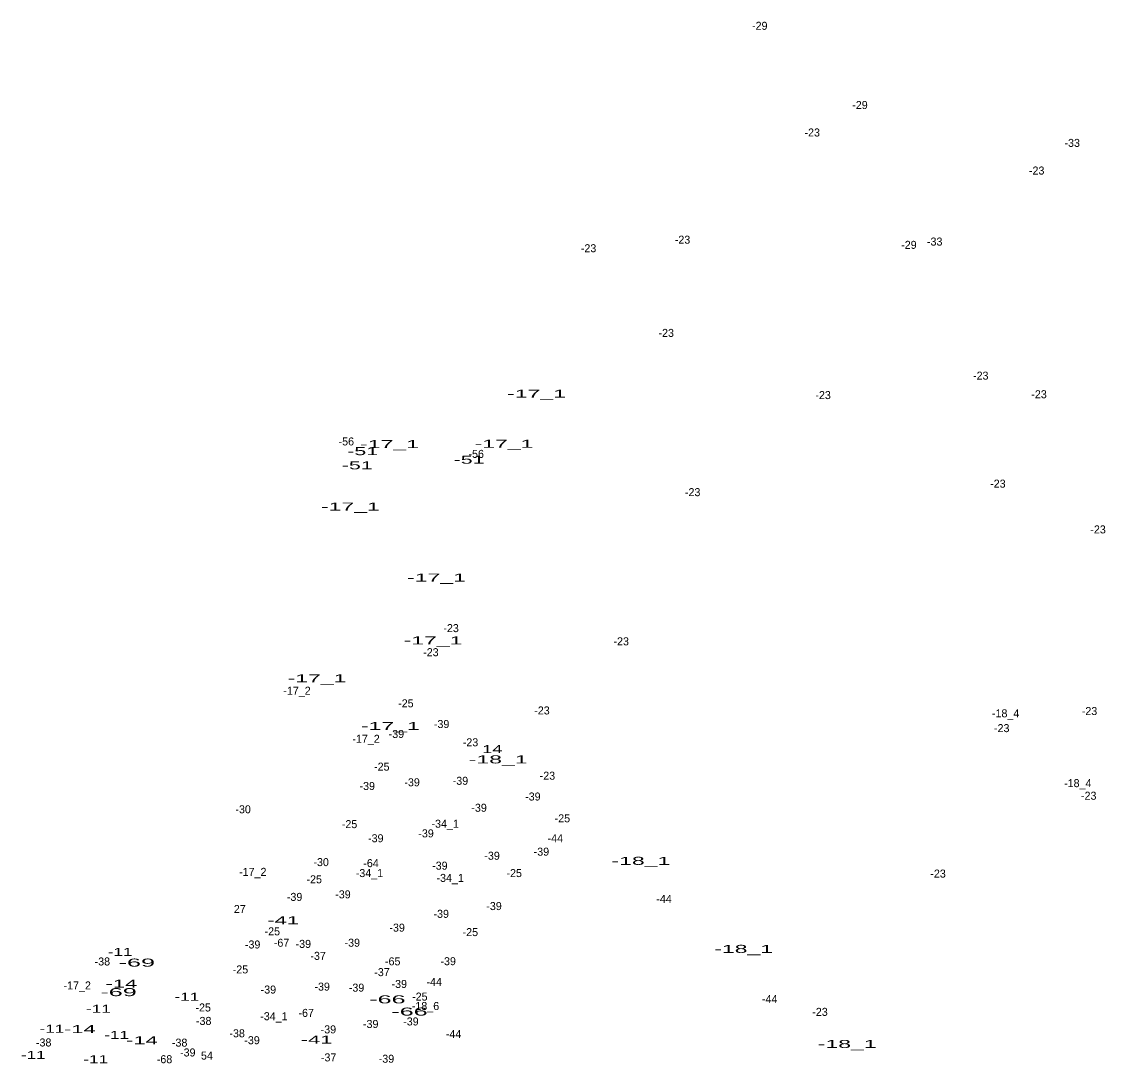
# Model space of a CAD drawing. Extents: x -657046 to -655830, y -1000534 to -999433.
# Drawn here: x -656878 to -656337, y -999954 to -999433 of the extents above; entities that cross this region are included whole.
import ezdxf
from ezdxf.enums import TextEntityAlignment as Align

# ---------------------------------------------------------------- set-up
doc = ezdxf.new("R2010")
doc.units = 0
doc.header["$LTSCALE"] = 1.6
doc.layers.add('24', color=7, linetype='Continuous')

msp = doc.modelspace()

# ---------------------------------------------------------------- texts
at = {"layer": '24'}
for s, p in [('-29', (-656509.52, -999437.12)), ('-29', (-656459.44, -999476.73)), ('-23', (-656483.305, -999490.46)), ('-33', (-656353.365, -999495.67)), ('-23', (-656371.115, -999509.49)), ('-23', (-656548.135, -999544.05)), ('-33', (-656422.085, -999544.99)), ('-23', (-656595.095, -999548.32)), ('-29', (-656434.98, -999546.63)), ('-23', (-656556.275, -999590.65)), ('-23', (-656399.065, -999612.01)), ('-23', (-656477.865, -999621.72)), ('-23', (-656369.935, -999621.31)), ('-56', (-656716.18, -999644.9)), ('-56', (-656651.25, -999651.12)), ('-23', (-656543.075, -999670.26)), ('-23', (-656390.515, -999666)), ('-23', (-656340.435, -999688.88)), ('-23', (-656663.805, -999738.22)), ('-23', (-656578.785, -999744.82)), ('-23', (-656673.895, -999750.26)), ('-17_2', (-656740.822, -999769.52)), ('-25', (-656686.405, -999775.82)), ('-23', (-656618.385, -999779.38)), ('-18_4', (-656386.63, -999780.82)), ('-23', (-656344.715, -999779.68)), ('-39', (-656668.55, -999786.18)), ('-23', (-656388.585, -999788.22)), ('-17_2', (-656706.312, -999793.56)), ('-39', (-656691.16, -999791.14)), ('-23', (-656654.105, -999795.3)), ('-25', (-656698.445, -999807.47)), ('-39', (-656683.3, -999815.3)), ('-39', (-656659.14, -999814.54)), ('-23', (-656615.665, -999812)), ('-18_4', (-656350.57, -999815.72)), ('-39', (-656705.72, -999817.15)), ('-23', (-656345.105, -999822.01)), ('-39', (-656622.94, -999822.4)), ('-30', (-656767.759, -999828.79)), ('-39', (-656649.82, -999828.03)), ('-25', (-656714.555, -999836.21)), ('-34_1', (-656666.77, -999836.01)), ('-25', (-656608.185, -999833.3)), ('-39', (-656701.45, -999843.27)), ('-39', (-656676.32, -999840.84)), ('-44', (-656611.703, -999843.27)), ('-39', (-656643.32, -999852.02)), ('-39', (-656618.67, -999849.98)), ('-17_2', (-656762.922, -999860.07)), ('-30', (-656728.749, -999855.2)), ('-64', (-656703.825, -999855.72)), ('-39', (-656669.42, -999856.97)), ('-25', (-656732.215, -999863.79)), ('-34_1', (-656704.62, -999860.68)), ('-34_1', (-656664.25, -999863.1)), ('-25', (-656632.255, -999860.68)), ('-23', (-656420.405, -999860.93)), ('-39', (-656742.03, -999872.58)), ('-39', (-656717.86, -999871.32)), ('-44', (-656557.353, -999873.56)), ('27', (-656769.413, -999878.62)), ('-39', (-656668.74, -999881.05)), ('-39', (-656642.35, -999877.17)), ('-25', (-656753.175, -999889.8)), ('-39', (-656690.78, -999887.95)), ('-25', (-656654.195, -999890.19)), ('-39', (-656763, -999896.37)), ('-67', (-656748.545, -999895.52)), ('-39', (-656737.67, -999896.08)), ('-39', (-656713.2, -999895.5)), ('-37', (-656730.261, -999902.05)), ('-38', (-656838.115, -999904.87)), ('-25', (-656769.095, -999908.84)), ('-65', (-656692.99, -999904.8)), ('-39', (-656665.26, -999904.74)), ('-37', (-656698.341, -999910.2)), ('-17_2', (-656850.672, -999916.85)), ('-39', (-656755.13, -999918.9)), ('-39', (-656728.25, -999917.44)), ('-39', (-656711.07, -999917.95)), ('-39', (-656689.71, -999916.1)), ('-44', (-656672.263, -999915.11)), ('-25', (-656679.425, -999922.42)), ('-44', (-656504.563, -999923.64)), ('-25', (-656787.725, -999927.87)), ('-67', (-656736.225, -999930.57)), ('-18_6', (-656676.602, -999927.13)), ('-23', (-656479.415, -999930.06)), ('-38', (-656787.455, -999934.58)), ('-34_1', (-656752.37, -999932.23)), ('-39', (-656683.89, -999934.84)), ('-38', (-656770.755, -999940.77)), ('-39', (-656725.14, -999938.82)), ('-39', (-656703.98, -999936.11)), ('-44', (-656662.563, -999941.13)), ('-38', (-656867.445, -999945.36)), ('-38', (-656799.485, -999945.43)), ('-39', (-656763.29, -999944.24)), ('-39', (-656795.41, -999950.35)), ('54', (-656785.841, -999951.92)), ('-68', (-656807.04, -999953.73)), ('-37', (-656725.021, -999952.82)), ('-39', (-656696.12, -999953.49))]:
    msp.add_text(s, height=4, dxfattribs=at).set_placement(p, align=Align.CENTER)
for s, width, p in [('-17_1', 2.15, (-656621.093, -999621.02)), ('-17_1', 2.15, (-656694.563, -999646.24)), ('-17_1', 2.15, (-656637.383, -999646.04)), ('-51', 2, (-656707.991, -999649.76)), ('-51', 2, (-656654.801, -999654.03)), ('-51', 2, (-656710.701, -999656.84)), ('-17_1', 2.15, (-656714.143, -999677.44)), ('-17_1', 2.15, (-656671.103, -999712.94)), ('-17_1', 2.15, (-656672.853, -999744.35)), ('-17_1', 2.15, (-656730.823, -999763.31)), ('-17_1', 2.15, (-656694.173, -999787.17)), ('14', 1.7, (-656643.213, -999798.71)), ('-18_1', 2.15, (-656640.287, -999803.85)), ('-18_1', 2.15, (-656568.937, -999854.56)), ('-41', 2.05, (-656747.736, -999884.3)), ('-11', 1.6, (-656829.217, -999900.07)), ('-18_1', 2.15, (-656517.577, -999898.58)), ('-69', 2.35, (-656820.893, -999905.43)), ('-14', 2.05, (-656828.606, -999915.98)), ('-69', 2.35, (-656830.013, -999920.19)), ('-11', 1.6, (-656795.877, -999922.48)), ('-66', 2.35, (-656695.633, -999923.81)), ('-11', 1.6, (-656840.077, -999928.49)), ('-66', 2.35, (-656684.573, -999929.92)), ('-11', 1.6, (-656863.337, -999938.48)), ('-14', 2.05, (-656849.346, -999938.67)), ('-11', 1.6, (-656830.967, -999941.57)), ('-14', 2.05, (-656818.326, -999944.3)), ('-41', 2.05, (-656731.046, -999943.9)), ('-18_1', 2.15, (-656465.817, -999946.1)), ('-11', 1.6, (-656872.637, -999951.57)), ('-11', 1.6, (-656841.427, -999953.71))]:
    msp.add_text(s, height=4, dxfattribs=dict(at, width=width)).set_placement(p, align=Align.CENTER)

doc.saveas('drawing.dxf')
